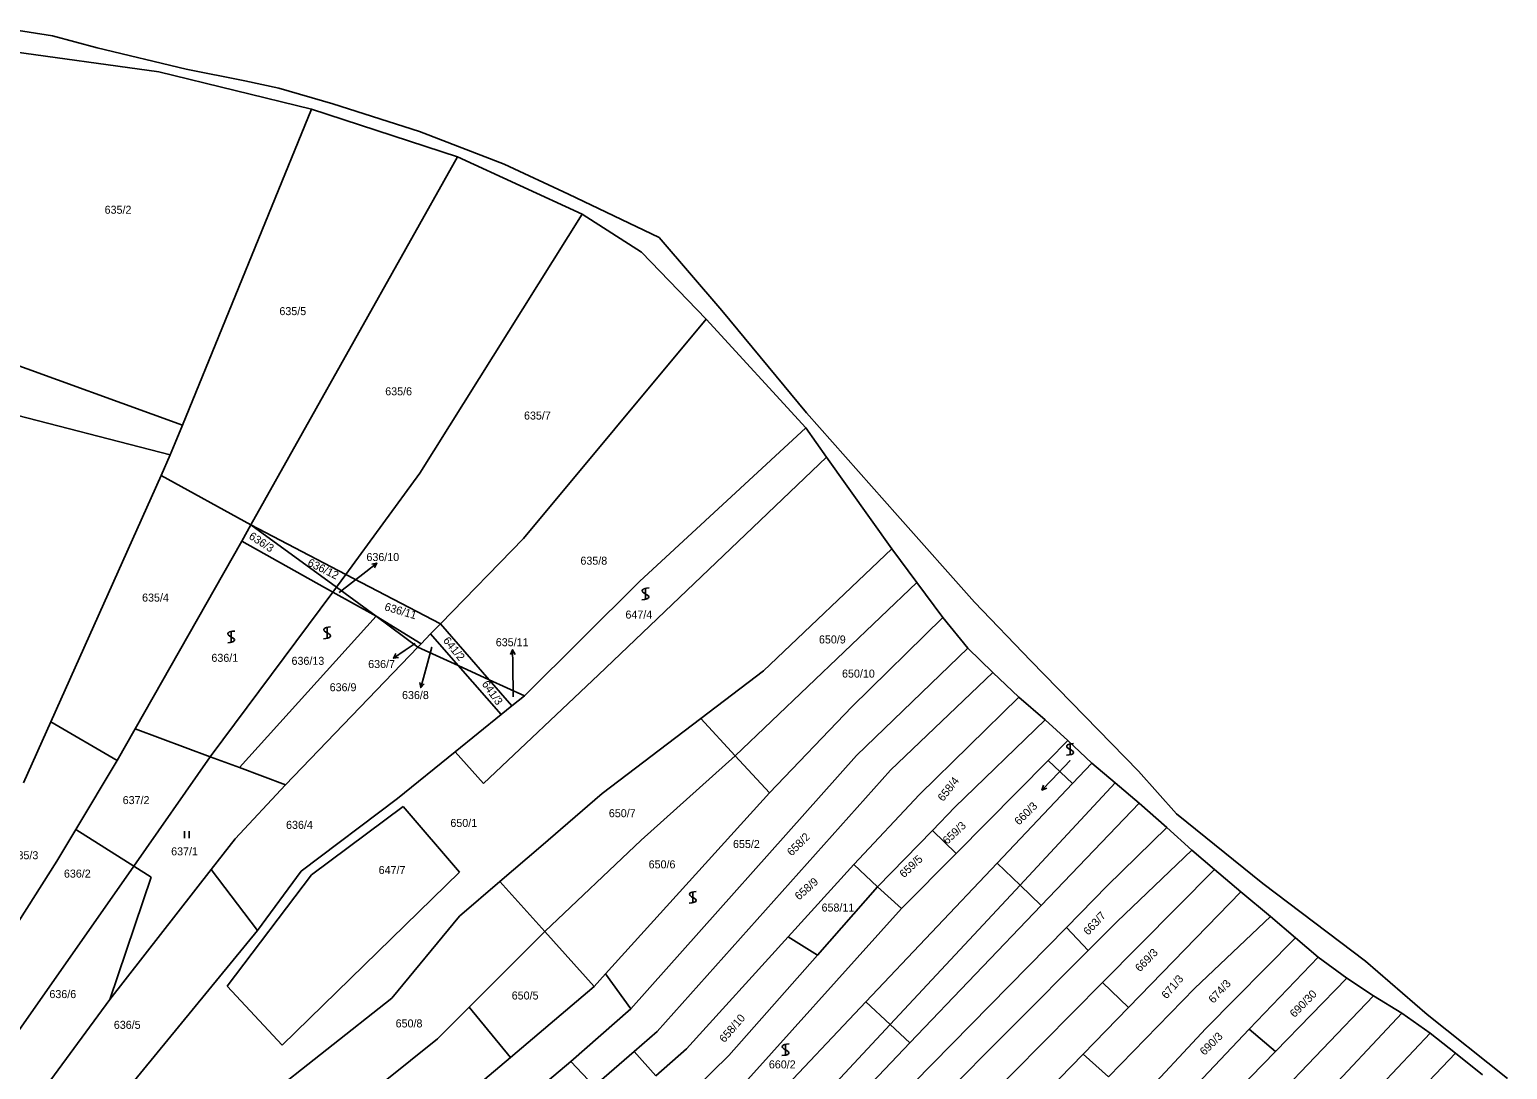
# Model space of a CAD drawing. Extents: x -580630 to -576196, y -1189024 to -1183567.
# Drawn here: x -577874.8 to -577560.9, y -1184612.4 to -1184391.6 of the extents above; entities that cross this region are included whole.
import ezdxf

# ---------------------------------------------------------------- set-up
doc = ezdxf.new("R2010")
doc.units = 0
for name, color, linetype in [('Vrstva 1', 7, 'Continuous'), ('Vrstva 13', 7, 'Continuous'), ('Vrstva 16', 7, 'Continuous'), ('Vrstva 18', 7, 'Continuous'), ('Vrstva 25', 7, 'Continuous'), ('Vrstva 4', 7, 'Continuous'), ('Vrstva 6', 7, 'Continuous')]:
    doc.layers.add(name, color=color, linetype=linetype)

msp = doc.modelspace()

# ---------------------------------------------------------------- linework, layer by layer
at = {"layer": 'Vrstva 1'}
for p, q in [((-577847.32, -1184400.54), (-577880.07, -1184396)), ((-577814.9, -1184408.5), (-577847.32, -1184400.54)), ((-577814.9, -1184408.5), (-577783.89, -1184418.63)), ((-577757.43, -1184430.76), (-577783.89, -1184418.63)), ((-577744.8, -1184438.86), (-577757.43, -1184430.76)), ((-577731.08, -1184453.09), (-577744.8, -1184438.86)), ((-577731.08, -1184453.09), (-577709.93, -1184476.19)), ((-577844.92, -1184481.89), (-577891.83, -1184469.8)), ((-577709.93, -1184476.19), (-577745.2, -1184508.79)), ((-577709.93, -1184476.19), (-577705.52, -1184482.39)), ((-577846.8, -1184486.31), (-577844.92, -1184481.89)), ((-577753.97, -1184528.59), (-577705.52, -1184482.39)), ((-577691.66, -1184501.87), (-577705.52, -1184482.39)), ((-577870.25, -1184538.6), (-577846.8, -1184486.31)), ((-577827.75, -1184496.8), (-577829.7, -1184500.24)), ((-577807.61, -1184507.29), (-577827.75, -1184496.8)), ((-577829.7, -1184500.24), (-577852.33, -1184540.11)), ((-577829.7, -1184500.24), (-577810.37, -1184511.06)), ((-577686.33, -1184509.03), (-577691.66, -1184501.87)), ((-577787.47, -1184517.78), (-577807.61, -1184507.29)), ((-577745.2, -1184508.79), (-577769.68, -1184533.09)), ((-577680.81, -1184516.45), (-577686.33, -1184509.03)), ((-577810.37, -1184511.06), (-577801.18, -1184516.2)), ((-577830.16, -1184548.34), (-577801.18, -1184516.2)), ((-577801.18, -1184516.2), (-577791.59, -1184522.01)), ((-577700.16, -1184535.42), (-577680.81, -1184516.45)), ((-577675.53, -1184522.94), (-577680.81, -1184516.45)), ((-577791.59, -1184522.01), (-577789.58, -1184519.95)), ((-577789.58, -1184519.95), (-577787.47, -1184517.78)), ((-577783.74, -1184526.64), (-577789.58, -1184519.95)), ((-577777.15, -1184529.67), (-577787.47, -1184517.78)), ((-577699.12, -1184545.76), (-577675.53, -1184522.94)), ((-577670.18, -1184528.13), (-577675.53, -1184522.94)), ((-577774.62, -1184537.08), (-577783.74, -1184526.64)), ((-577778.33, -1184551.67), (-577753.97, -1184528.59)), ((-577664.66, -1184533.37), (-577670.18, -1184528.13)), ((-577772.32, -1184535.22), (-577777.15, -1184529.67)), ((-577772.32, -1184535.22), (-577774.62, -1184537.08)), ((-577769.68, -1184533.09), (-577772.32, -1184535.22)), ((-577717.63, -1184553.69), (-577700.16, -1184535.42)), ((-577685.78, -1184554.01), (-577664.66, -1184533.37)), ((-577664.66, -1184533.37), (-577659.1, -1184538.16)), ((-577876.07, -1184551.58), (-577870.25, -1184538.6)), ((-577774.62, -1184537.08), (-577784.4, -1184544.98)), ((-577659.1, -1184538.16), (-577678.23, -1184556.74)), ((-577654.24, -1184542.6), (-577659.1, -1184538.16)), ((-577852.33, -1184540.11), (-577856.15, -1184546.85)), ((-577836.38, -1184546.01), (-577852.33, -1184540.11)), ((-577784.4, -1184544.98), (-577796.65, -1184554.89)), ((-577778.33, -1184551.67), (-577784.4, -1184544.98)), ((-577658.44, -1184546.84), (-577654.24, -1184542.6)), ((-577649.19, -1184547.39), (-577654.24, -1184542.6)), ((-577856.15, -1184546.85), (-577864.95, -1184561.46)), ((-577830.16, -1184548.34), (-577836.38, -1184546.01)), ((-577820.38, -1184552), (-577830.16, -1184548.34)), ((-577747.05, -1184599.54), (-577699.12, -1184545.76)), ((-577677.99, -1184566.55), (-577658.44, -1184546.84)), ((-577653.24, -1184551.68), (-577658.44, -1184546.84)), ((-577653.24, -1184551.68), (-577649.19, -1184547.39)), ((-577644.2, -1184551.58), (-577649.19, -1184547.39)), ((-577639.11, -1184555.87), (-577644.2, -1184551.58)), ((-577831.09, -1184563.46), (-577820.38, -1184552)), ((-577752.43, -1184592.12), (-577717.63, -1184553.69)), ((-577699.7, -1184568.93), (-577685.78, -1184554.01)), ((-577669.29, -1184568.65), (-577653.24, -1184551.68)), ((-577796.65, -1184554.89), (-577817.07, -1184570.33)), ((-577795.43, -1184556.61), (-577814.92, -1184571.1)), ((-577783.47, -1184570.51), (-577795.43, -1184556.61)), ((-577678.23, -1184556.74), (-577683.01, -1184561.67)), ((-577633.22, -1184561.04), (-577639.11, -1184555.87)), ((-577864.95, -1184561.46), (-577868.99, -1184568.18)), ((-577852.65, -1184569.25), (-577864.95, -1184561.46)), ((-577836.19, -1184569.99), (-577831.09, -1184563.46)), ((-577683.01, -1184561.67), (-577694.66, -1184573.66)), ((-577683.01, -1184561.67), (-577677.99, -1184566.55)), ((-577627.96, -1184565.83), (-577633.22, -1184561.04)), ((-577689.59, -1184578.26), (-577677.99, -1184566.55)), ((-577643.81, -1184581.01), (-577627.96, -1184565.83)), ((-577623.1, -1184569.95), (-577627.96, -1184565.83)), ((-577868.99, -1184568.18), (-577888.82, -1184599.48)), ((-577857.74, -1184597.59), (-577836.19, -1184569.99)), ((-577848.95, -1184571.59), (-577852.65, -1184569.25)), ((-577817.07, -1184570.33), (-577826.37, -1184582.89)), ((-577713.63, -1184584.26), (-577699.7, -1184568.93)), ((-577697.13, -1184598.08), (-577669.29, -1184568.65)), ((-577646.87, -1184593.95), (-577623.1, -1184569.95)), ((-577617.55, -1184574.74), (-577623.1, -1184569.95)), ((-577857.74, -1184597.59), (-577848.95, -1184571.59)), ((-577814.92, -1184571.1), (-577832.79, -1184594.74)), ((-577821.13, -1184607.3), (-577783.47, -1184570.51)), ((-577694.66, -1184573.66), (-577707.45, -1184588.13)), ((-577641.38, -1184599.25), (-577617.55, -1184574.74)), ((-577611.25, -1184579.93), (-577617.55, -1184574.74)), ((-577726.75, -1184619.54), (-577689.59, -1184578.26)), ((-577853.5, -1184615.96), (-577826.37, -1184582.89)), ((-577708.51, -1184637.17), (-577654.58, -1184582.28)), ((-577649.93, -1184587.15), (-577654.58, -1184582.28)), ((-577649.93, -1184587.15), (-577643.81, -1184581.01)), ((-577627.3, -1184595.2), (-577611.25, -1184579.93)), ((-577605.92, -1184584.48), (-577611.25, -1184579.93)), ((-577707.45, -1184588.13), (-577713.63, -1184584.26)), ((-577624.92, -1184603.73), (-577605.92, -1184584.48)), ((-577601.13, -1184588.56), (-577605.92, -1184584.48)), ((-577707.45, -1184588.13), (-577726.28, -1184609.44)), ((-577697.57, -1184634.99), (-577649.93, -1184587.15)), ((-577601.13, -1184588.56), (-577595.03, -1184593.04)), ((-577754.85, -1184594.79), (-577752.43, -1184592.12)), ((-577832.79, -1184594.74), (-577821.13, -1184607.3)), ((-577772.62, -1184609.9), (-577754.85, -1184594.79)), ((-577697.48, -1184645.05), (-577646.87, -1184593.95)), ((-577641.38, -1184599.25), (-577646.87, -1184593.95)), ((-577645.6, -1184613.98), (-577627.3, -1184595.2)), ((-577595.03, -1184593.04), (-577589.33, -1184596.8)), ((-577721.07, -1184623.39), (-577697.13, -1184598.08)), ((-577589.33, -1184596.8), (-577583.33, -1184600.46)), ((-577747.05, -1184599.54), (-577759.79, -1184610.76)), ((-577651.02, -1184609.17), (-577641.38, -1184599.25)), ((-577577.28, -1184604.75), (-577583.33, -1184600.46)), ((-577639.35, -1184619.15), (-577624.92, -1184603.73)), ((-577634.28, -1184623.43), (-577615.72, -1184603.91)), ((-577610.18, -1184608.62), (-577615.72, -1184603.91)), ((-577571.95, -1184609.01), (-577577.28, -1184604.75)), ((-577772.62, -1184609.9), (-577788.81, -1184623.53)), ((-577759.79, -1184610.76), (-577777.55, -1184625.57)), ((-577726.28, -1184609.44), (-577733.36, -1184616.43)), ((-577683.61, -1184642.69), (-577651.02, -1184609.17)), ((-577610.18, -1184608.62), (-577648.34, -1184647.87)), ((-577566.23, -1184613.55), (-577571.95, -1184609.01))]:
    msp.add_line(p, q, dxfattribs=at)
at = {"layer": 'Vrstva 13'}
for p, q in [((-577878.47, -1184391.58), (-577869.87, -1184392.91)), ((-577869.87, -1184392.91), (-577860.43, -1184395.43)), ((-577860.43, -1184395.43), (-577841.52, -1184399.98)), ((-577841.52, -1184399.98), (-577829.05, -1184402.5)), ((-577829.05, -1184402.5), (-577821.81, -1184404)), ((-577821.81, -1184404), (-577810.35, -1184407.36)), ((-577810.35, -1184407.36), (-577791.98, -1184413.25)), ((-577791.98, -1184413.25), (-577773.95, -1184420.14)), ((-577773.95, -1184420.14), (-577760.3, -1184426.52)), ((-577760.3, -1184426.52), (-577741.08, -1184435.77)), ((-577741.08, -1184435.77), (-577727.77, -1184451.28)), ((-577727.77, -1184451.28), (-577709.73, -1184472.99)), ((-577709.73, -1184472.99), (-577690.47, -1184494.81)), ((-577690.47, -1184494.81), (-577674.11, -1184513.17)), ((-577674.11, -1184513.17), (-577662.15, -1184525.63)), ((-577662.15, -1184525.63), (-577639.28, -1184549.07)), ((-577639.28, -1184549.07), (-577631.18, -1184558.17)), ((-577631.18, -1184558.17), (-577612.82, -1184572.97)), ((-577612.82, -1184572.97), (-577591.07, -1184589.47)), ((-577591.07, -1184589.47), (-577577.93, -1184600.75)), ((-577577.93, -1184600.75), (-577560.9, -1184614.39))]:
    msp.add_line(p, q, dxfattribs=at)
at = {"layer": 'Vrstva 16'}
for p, q in [((-577808.98, -1184511.14), (-577803.37, -1184506.77)), ((-577801.005, -1184504.924), (-577803.37, -1184506.77)), ((-577792.9, -1184521.95), (-577795.01, -1184523.38)), ((-577789.33, -1184522.76), (-577790.89, -1184528.45)), ((-577772.172, -1184523.3), (-577772.13, -1184526.3)), ((-577797.494, -1184525.062), (-577795.01, -1184523.38)), ((-577772.04, -1184533.31), (-577772.13, -1184526.3)), ((-577791.686, -1184531.342), (-577790.89, -1184528.45)), ((-577653.8, -1184546.82), (-577657.69, -1184550.92)), ((-577659.754, -1184553.097), (-577657.69, -1184550.92))]:
    msp.add_line(p, q, dxfattribs=at)
for points in [[(-577802.101, -1184505.145), (-577801.005, -1184504.924), (-577801.486, -1184505.934)], [(-577772.658, -1184524.307), (-577772.172, -1184523.3), (-577771.658, -1184524.293)], [(-577796.386, -1184524.915), (-577797.494, -1184525.062), (-577796.946, -1184524.087)], [(-577790.939, -1184530.511), (-577791.686, -1184531.342), (-577791.903, -1184530.246)], [(-577658.703, -1184552.716), (-577659.754, -1184553.097), (-577659.429, -1184552.028)]]:
    msp.add_lwpolyline(points, dxfattribs=at)
at = {"layer": 'Vrstva 25'}
for p, q in [((-577841.89, -1184561.81), (-577841.89, -1184563.31)), ((-577840.89, -1184563.31), (-577840.89, -1184561.81))]:
    msp.add_line(p, q, dxfattribs=at)
for points in [[(-577743.2, -1184510.18), (-577743.71, -1184510.24), (-577744.06, -1184510.29), (-577744.3, -1184510.37), (-577744.48, -1184510.48), (-577744.6, -1184510.57), (-577744.65, -1184510.74), (-577744.6, -1184510.97), (-577744.21, -1184511.29), (-577743.65, -1184511.6), (-577743.3, -1184511.87), (-577743.23, -1184512.07), (-577743.3, -1184512.27), (-577743.46, -1184512.4), (-577743.65, -1184512.47), (-577744.18, -1184512.6), (-577744.7, -1184512.67)], [(-577743.95, -1184512.68), (-577743.95, -1184511.41), (-577743.95, -1184510.18)], [(-577831.19, -1184519.32), (-577831.7, -1184519.38), (-577832.05, -1184519.43), (-577832.29, -1184519.51), (-577832.47, -1184519.62), (-577832.59, -1184519.71), (-577832.64, -1184519.88), (-577832.59, -1184520.11), (-577832.2, -1184520.43), (-577831.64, -1184520.74), (-577831.29, -1184521.01), (-577831.22, -1184521.21), (-577831.29, -1184521.41), (-577831.45, -1184521.54), (-577831.64, -1184521.61), (-577832.17, -1184521.74), (-577832.69, -1184521.81)], [(-577831.94, -1184521.82), (-577831.94, -1184520.55), (-577831.94, -1184519.32)], [(-577810.83, -1184518.46), (-577811.34, -1184518.52), (-577811.69, -1184518.57), (-577811.93, -1184518.65), (-577812.11, -1184518.76), (-577812.23, -1184518.85), (-577812.28, -1184519.02), (-577812.23, -1184519.25), (-577811.84, -1184519.57), (-577811.28, -1184519.88), (-577810.93, -1184520.15), (-577810.86, -1184520.35), (-577810.93, -1184520.55), (-577811.09, -1184520.68), (-577811.28, -1184520.75), (-577811.81, -1184520.88), (-577812.33, -1184520.95)], [(-577811.58, -1184520.96), (-577811.58, -1184519.69), (-577811.58, -1184518.46)], [(-577653.05, -1184543.22), (-577653.56, -1184543.28), (-577653.91, -1184543.33), (-577654.15, -1184543.41), (-577654.33, -1184543.52), (-577654.45, -1184543.61), (-577654.5, -1184543.78), (-577654.45, -1184544.01), (-577654.06, -1184544.33), (-577653.5, -1184544.64), (-577653.15, -1184544.91), (-577653.08, -1184545.11), (-577653.15, -1184545.31), (-577653.31, -1184545.44), (-577653.5, -1184545.51), (-577654.03, -1184545.64), (-577654.55, -1184545.71)], [(-577653.8, -1184545.72), (-577653.8, -1184544.45), (-577653.8, -1184543.22)], [(-577733.16, -1184574.64), (-577733.67, -1184574.7), (-577734.02, -1184574.75), (-577734.26, -1184574.83), (-577734.44, -1184574.94), (-577734.56, -1184575.03), (-577734.61, -1184575.2), (-577734.56, -1184575.43), (-577734.17, -1184575.75), (-577733.61, -1184576.06), (-577733.26, -1184576.33), (-577733.19, -1184576.53), (-577733.26, -1184576.73), (-577733.42, -1184576.86), (-577733.61, -1184576.93), (-577734.14, -1184577.06), (-577734.66, -1184577.13)], [(-577733.91, -1184577.14), (-577733.91, -1184575.87), (-577733.91, -1184574.64)], [(-577713.47, -1184607.01), (-577713.98, -1184607.07), (-577714.33, -1184607.12), (-577714.57, -1184607.2), (-577714.75, -1184607.31), (-577714.87, -1184607.4), (-577714.92, -1184607.57), (-577714.87, -1184607.8), (-577714.48, -1184608.12), (-577713.92, -1184608.43), (-577713.57, -1184608.7), (-577713.5, -1184608.9), (-577713.57, -1184609.1), (-577713.73, -1184609.23), (-577713.92, -1184609.3), (-577714.45, -1184609.43), (-577714.97, -1184609.5)], [(-577714.22, -1184609.51), (-577714.22, -1184608.24), (-577714.22, -1184607.01)]]:
    msp.add_lwpolyline(points, dxfattribs=at)
at = {"layer": 'Vrstva 4'}
for p, q in [((-577664.42, -1184573.3), (-577669.29, -1184568.65)), ((-577659.9, -1184577.62), (-577664.42, -1184573.3)), ((-577691.97, -1184602.89), (-577697.13, -1184598.08)), ((-577687.79, -1184606.79), (-577691.97, -1184602.89))]:
    msp.add_line(p, q, dxfattribs=at)
at = {"layer": 'Vrstva 6'}
for p, q in [((-577842.25, -1184475.61), (-577814.9, -1184408.5)), ((-577783.89, -1184418.63), (-577827.75, -1184496.8)), ((-577757.43, -1184430.76), (-577791.87, -1184485.78)), ((-577769.87, -1184499.7), (-577731.08, -1184453.09)), ((-577842.25, -1184475.61), (-577889.52, -1184458.51)), ((-577843.84, -1184479.34), (-577842.25, -1184475.61)), ((-577844.92, -1184481.89), (-577843.84, -1184479.34)), ((-577827.75, -1184496.8), (-577846.8, -1184486.31)), ((-577791.87, -1184485.78), (-577807.61, -1184507.29)), ((-577809.6, -1184510.02), (-577827.75, -1184496.8)), ((-577787.47, -1184517.78), (-577769.87, -1184499.7)), ((-577718.91, -1184527.75), (-577691.66, -1184501.87)), ((-577807.61, -1184507.29), (-577809.6, -1184510.02)), ((-577809.6, -1184510.02), (-577810.37, -1184511.06)), ((-577801.18, -1184516.2), (-577809.6, -1184510.02)), ((-577686.33, -1184509.03), (-577724.9, -1184545.82)), ((-577810.37, -1184511.06), (-577836.38, -1184546.01)), ((-577792.28, -1184522.72), (-577801.18, -1184516.2)), ((-577820.38, -1184552), (-577792.28, -1184522.72)), ((-577792.28, -1184522.72), (-577791.59, -1184522.01)), ((-577783.74, -1184526.64), (-577792.28, -1184522.72)), ((-577777.15, -1184529.67), (-577783.74, -1184526.64)), ((-577732.23, -1184537.89), (-577718.91, -1184527.75)), ((-577691.9, -1184548.88), (-577670.18, -1184528.13)), ((-577769.68, -1184533.09), (-577777.15, -1184529.67)), ((-577870.25, -1184538.6), (-577856.15, -1184546.85)), ((-577753.17, -1184553.83), (-577732.23, -1184537.89)), ((-577732.23, -1184537.89), (-577724.9, -1184545.82)), ((-577852.65, -1184569.25), (-577836.38, -1184546.01)), ((-577724.9, -1184545.82), (-577744.88, -1184563.76)), ((-577717.63, -1184553.69), (-577724.9, -1184545.82)), ((-577741.45, -1184604.4), (-577691.9, -1184548.88)), ((-577664.42, -1184573.3), (-577644.2, -1184551.58)), ((-577766.2, -1184565.05), (-577753.17, -1184553.83)), ((-577659.9, -1184577.62), (-577639.11, -1184555.87)), ((-577744.88, -1184563.76), (-577765.35, -1184583.16)), ((-577645.88, -1184573.42), (-577633.22, -1184561.04)), ((-577774.92, -1184572.55), (-577766.2, -1184565.05)), ((-577881.57, -1184610.53), (-577852.65, -1184569.25)), ((-577836.19, -1184569.99), (-577826.37, -1184582.89)), ((-577694.66, -1184573.66), (-577699.7, -1184568.93)), ((-577783.46, -1184579.91), (-577774.92, -1184572.55)), ((-577774.92, -1184572.55), (-577765.35, -1184583.16)), ((-577691.97, -1184602.89), (-577664.42, -1184573.3)), ((-577654.58, -1184582.28), (-577645.88, -1184573.42)), ((-577689.59, -1184578.26), (-577694.66, -1184573.66)), ((-577687.79, -1184606.79), (-577659.9, -1184577.62)), ((-577797.8, -1184597.29), (-577783.46, -1184579.91)), ((-577765.35, -1184583.16), (-577781.39, -1184599.21)), ((-577754.85, -1184594.79), (-577765.35, -1184583.16)), ((-577735.24, -1184608.04), (-577713.63, -1184584.26)), ((-577615.72, -1184603.91), (-577601.13, -1184588.56)), ((-577752.43, -1184592.12), (-577747.05, -1184599.54)), ((-577595.03, -1184593.04), (-577610.18, -1184608.62)), ((-577875.24, -1184621.44), (-577857.74, -1184597.59)), ((-577825.44, -1184619.12), (-577797.8, -1184597.29)), ((-577589.33, -1184596.8), (-577638.74, -1184648.36)), ((-577788.12, -1184605.95), (-577781.39, -1184599.21)), ((-577781.39, -1184599.21), (-577772.62, -1184609.9)), ((-577583.33, -1184600.46), (-577633.33, -1184653.72)), ((-577746.39, -1184608.65), (-577741.45, -1184604.4)), ((-577725.12, -1184638.34), (-577691.97, -1184602.89)), ((-577619.1, -1184648.87), (-577577.28, -1184604.75)), ((-577817.28, -1184629.24), (-577788.12, -1184605.95)), ((-577741.75, -1184613.77), (-577735.24, -1184608.04)), ((-577713.02, -1184633.18), (-577687.79, -1184606.79)), ((-577754.88, -1184615.96), (-577759.79, -1184610.76)), ((-577754.88, -1184615.96), (-577746.39, -1184608.65)), ((-577746.39, -1184608.65), (-577741.75, -1184613.77)), ((-577651.02, -1184609.17), (-577645.6, -1184613.98)), ((-577596.36, -1184634.53), (-577571.95, -1184609.01))]:
    msp.add_line(p, q, dxfattribs=at)

# ---------------------------------------------------------------- texts
at = {"layer": 'Vrstva 16'}
for s, p in [('636/10', (-577803.218, -1184504.46)), ('635/11', (-577775.75, -1184522.55)), ('636/7', (-577802.85, -1184527.18)), ('636/8', (-577795.66, -1184533.77))]:
    msp.add_text(s, height=1.7, dxfattribs=at).set_placement(p)
msp.add_text('660/3', height=1.7, rotation=44.91989, dxfattribs=at).set_placement((-577664.611, -1184560.671))
at = {"layer": 'Vrstva 18'}
for s, height, p in [('635/2', 1.7, (-577858.821, -1184430.7)), ('635/5', 1.7, (-577821.704, -1184452.23)), ('635/6', 1.7, (-577799.227, -1184469.26)), ('635/7', 1.7, (-577769.757, -1184474.41)), ('635/8', 1.7, (-577757.777, -1184505.23)), ('635/4', 1.7, (-577850.867, -1184513.07)), ('636/10', 0.1, (-577809.209, -1184511.14)), ('647/4', 1.7, (-577748.213, -1184516.68)), ('650/9', 1.7, (-577707.117, -1184521.96)), ('636/7', 0.1, (-577793.105, -1184521.95)), ('636/8', 0.1, (-577789.538, -1184522.76)), ('636/1', 1.7, (-577836.142, -1184525.86)), ('636/13', 1.7, (-577819.128, -1184526.5)), ('650/10', 1.7, (-577702.215, -1184529.21)), ('636/9', 1.7, (-577811.03, -1184532.11)), ('635/11', 0.1, (-577772.249, -1184533.31)), ('660/3', 0.1, (-577654.009, -1184546.82)), ('637/2', 1.7, (-577854.984, -1184556.08)), ('650/7', 1.7, (-577751.737, -1184558.86)), ('636/4', 1.7, (-577820.29, -1184561.34)), ('650/1', 1.7, (-577785.389, -1184560.93)), ('655/2', 1.7, (-577725.371, -1184565.4)), ('635/3', 1.7, (-577878.594, -1184567.79)), ('637/1', 1.7, (-577844.692, -1184566.96)), ('636/2', 1.7, (-577867.464, -1184571.69)), ('647/7', 1.7, (-577800.623, -1184570.92)), ('650/6', 1.7, (-577743.287, -1184569.73)), ('658/11', 1.7, (-577706.56, -1184578.9)), ('636/6', 1.7, (-577870.55, -1184597.28)), ('650/5', 1.7, (-577772.364, -1184597.58)), ('650/8', 1.7, (-577797.017, -1184603.51)), ('636/5', 1.7, (-577856.867, -1184603.81)), ('660/2', 1.7, (-577717.754, -1184612.21))]:
    msp.add_text(s, height=height, dxfattribs=at).set_placement(p)
for s, rotation, p in [('636/3', 326.98701, (-577828.345, -1184499.585)), ('636/12', 333.69062, (-577815.877, -1184505.346)), ('636/11', 343.4309, (-577799.518, -1184514.868)), ('641/2', 308.82425, (-577787.05, -1184521.389)), ('641/3', 305.10003, (-577778.794, -1184530.575)), ('658/4', 52.31105, (-577680.724, -1184555.645)), ('659/3', 43.31561, (-577679.875, -1184564.747)), ('658/2', 45.03448, (-577712.9, -1184567.223)), ('659/5', 43.31561, (-577689.056, -1184571.85)), ('658/9', 41.65403, (-577711.34, -1184576.581)), ('663/7', 47.15443, (-577649.916, -1184584.061)), ('669/3', 45.72203, (-577638.948, -1184591.82)), ('671/3', 49.56085, (-577633.272, -1184597.584)), ('674/3', 47.72738, (-577623.331, -1184598.515)), ('690/30', 45.55014, (-577606.105, -1184601.523)), ('658/10', 49.21708, (-577727.191, -1184606.864)), ('690/3', 45.03448, (-577625.237, -1184609.57))]:
    msp.add_text(s, height=1.7, rotation=rotation, dxfattribs=at).set_placement(p)

doc.saveas('drawing.dxf')
